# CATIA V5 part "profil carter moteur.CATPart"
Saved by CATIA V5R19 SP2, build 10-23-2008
Part number: profil carter moteur
Bounding box of the stored display mesh (mm): x -35 to 35, y -34 to 34, z 0 to 135
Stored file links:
  Z:\fausse table rondelle-20220905T211342Z-001\fausse table rondelle\profil carter moteur.CATPart
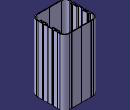
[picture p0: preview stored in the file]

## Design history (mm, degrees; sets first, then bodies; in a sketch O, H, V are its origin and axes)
AxisSystem1: origin (0, 0, 0), X (1, 0, 0), Y (0, 1, 0), Z (0, 0, 1)
Body1 (main body)
  Sketch1 on XY plane of AxisSystem1, origin (0, 0, 0), H (1, 0, 0), V (0, 1, 0)
    line L1 (-25, 34) -> (-20.2, 34)
    line L2 (-35, 0.2) -> (-35, 8.4)
    arc A1 centre (-25, 24) radius 10 from (-25, 34) to (-35, 24) ccw
    point P1 (-25, 34)
    point P2 (-35, 24)
    line L3 (-20.2, 34) -> (-20, 33.8)
    point P4 (-20, 33.8)
    line L4 (-20, 33.8) -> (-19.8, 34)
    construction line L5 (-20, 40.5053) -> (-20, 28.8065)
    point P5 (-20, 40.5053)
    point P6 (-20, 28.8065)
    line L6 (-19.8, 34) -> (-0.2, 34)
    point P7 (-20.2, 34)
    point P8 (-19.8, 34)
    construction line L7 (0, 34) -> (0, 0)
    construction line L8 (-35, 0) -> (38.6581, 0)
    point P9 (38.6581, 0)
    point P10 (0, 0)
    point P11 (0, 34)
    point P12 (-35, 0)
    line L9 (-0.2, 34) -> (0, 33.8)
    point P13 (0, 33.8)
    point P14 (-0.2, 34)
    reference projected line E1 through (0, 0) direction (0, 1) from edge [YZ plane of AxisSystem1 | XY plane of AxisSystem1]
    point P15 (0, 32.5)
    line L10 (0, 32.5) -> (-25, 32.5)
    point P16 (-25, 32.5)
    arc A2 centre (-25, 24) radius 8.5 from (-25, 32.5) to (-33.5, 24) ccw
    point P18 (-33.5, 24)
    line L11 (-33.5, 24) -> (-33.5, 19.15)
    point P19 (-33.5, 19.15)
    line L12 (-33.5, 19.15) -> (-30, 19.15)
    point P20 (-30, 19.15)
    line L13 (-30, 19.15) -> (-30, 17)
    point P21 (-30, 17)
    line L14 (-30, 17) -> (-30.6876, 17)
    point P22 (-30.6876, 17)
    arc A3 centre (-32, 16) radius 1.65 from (-30.6876, 17) to (-30.6876, 15) ccw
    point P23 (-32, 16)
    point P24 (-30.6876, 15)
    line L15 (-30.6876, 15) -> (-30, 15)
    point P25 (-30, 15)
    line L16 (-30, 15) -> (-30, 5.65)
    point P26 (-30, 5.65)
    line L17 (-30, 5.65) -> (-33.5, 5.65)
    point P27 (-33.5, 5.65)
    line L18 (-33.5, 5.65) -> (-33.5, 0)
    point P28 (-33.5, 0)
    construction line L19 (-39.3209, 20) -> (-28.5194, 20)
    point P29 (-39.3209, 20)
    point P30 (-28.5194, 20)
    construction line L20 (-39.519, 10) -> (-27.1443, 10)
    point P31 (-39.519, 10)
    point P32 (-27.1443, 10)
    axis line L21 (-33.2034, 16) -> (-30.7966, 16)
    point P33 (-33.2034, 16)
    point P34 (-30.7966, 16)
    reference projected line E2 through (0, 0) direction (1, 0) from edge [XY plane of AxisSystem1 | ZX plane of AxisSystem1]
    point P35 (-33.5, 13)
    line L22 (-33.5, 13) -> (-31.5, 13)
    line L23 (-31.5, 13) -> (-31.5, 7)
    line L24 (-31.5, 7) -> (-33.5, 7)
    line L25 (-33.5, 7) -> (-33.5, 8.4)
    point P36 (-31.5, 13)
    point P37 (-31.5, 7)
    point P38 (-33.5, 7)
    line L26 (-35, 11.6) -> (-33.5, 11.6)
    line L27 (-33.5, 8.4) -> (-35, 8.4)
    line L28 (-35, 11.6) -> (-35, 19.8)
    line L29 (-33.5, 11.6) -> (-33.5, 13)
    point P39 (-35, 8.4)
    point P40 (-35, 11.6)
    point P41 (-33.5, 11.6)
    point P42 (-33.5, 8.4)
    line L30 (-35, 19.8) -> (-34.8, 20)
    point P43 (-34.8, 20)
    line L31 (-34.8, 20) -> (-35, 20.2)
    line L32 (-35, 20.2) -> (-35, 24)
    point P44 (-35, 19.8)
    point P45 (-35, 20.2)
    line L33 (-35, 0.2) -> (-34.8, 0)
    point P46 (-34.8, 0)
    point P47 (-35, 0.2)
    reference projected line E3 through (0, 0) direction (0, 1) from edge [YZ plane of AxisSystem1 | XY plane of AxisSystem1]
    point P50 (0, 0)
    construction line L34 through (0, 0) direction (0, 1)
    point P53 (25, 34)
    point P54 (35, 24)
    point P56 (20, 33.8)
    point P57 (20, 28.8065)
    point P58 (20, 40.5053)
    construction line L35 (20, 40.5053) -> (20, 28.8065)
    point P59 (20.2, 34)
    point P60 (19.8, 34)
    point P61 (0, 0)
    point P62 (0, 34)
    construction line L36 (0, 34) -> (0, 0)
    point P63 (35, 0)
    point P64 (0, 33.8)
    point P65 (0.2, 34)
    point P66 (0, 32.5)
    point P67 (25, 32.5)
    point P69 (33.5, 24)
    point P70 (33.5, 19.15)
    point P71 (30, 19.15)
    point P72 (30, 17)
    point P73 (30.6876, 17)
    point P75 (30.6876, 15)
    point P76 (30, 15)
    point P77 (30, 5.65)
    point P78 (33.5, 5.65)
    point P79 (33.5, 0)
    point P80 (28.5194, 20)
    point P81 (39.3209, 20)
    construction line L37 (39.3209, 20) -> (28.5194, 20)
    point P82 (27.1443, 10)
    point P83 (39.519, 10)
    construction line L38 (39.519, 10) -> (27.1443, 10)
    point P84 (30.7966, 16)
    point P85 (33.2034, 16)
    construction line L39 (33.2034, 16) -> (30.7966, 16)
    point P86 (33.5, 13)
    point P87 (31.5, 13)
    point P88 (31.5, 7)
    point P89 (33.5, 7)
    point P90 (35, 8.4)
    point P91 (35, 11.6)
    point P92 (33.5, 11.6)
    point P93 (33.5, 8.4)
    point P94 (34.8, 20)
    point P95 (35, 19.8)
    point P96 (35, 20.2)
    point P97 (34.8, 0)
    point P98 (35, 0.2)
    line L40 (25, 34) -> (20.2, 34)
    line L41 (35, 0.2) -> (35, 8.4)
    arc A4 centre (25, 24) radius 10 from (25, 34) to (35, 24) cw
    line L42 (20.2, 34) -> (20, 33.8)
    line L43 (20, 33.8) -> (19.8, 34)
    line L44 (19.8, 34) -> (0.2, 34)
    line L45 (0.2, 34) -> (0, 33.8)
    line L46 (0, 32.5) -> (25, 32.5)
    arc A5 centre (25, 24) radius 8.5 from (25, 32.5) to (33.5, 24) cw
    line L47 (33.5, 24) -> (33.5, 19.15)
    line L48 (33.5, 19.15) -> (30, 19.15)
    line L49 (30, 19.15) -> (30, 17)
    line L50 (30, 17) -> (30.6876, 17)
    arc A6 centre (32, 16) radius 1.65 from (30.6876, 17) to (30.6876, 15) cw
    line L51 (30.6876, 15) -> (30, 15)
    line L52 (30, 15) -> (30, 5.65)
    line L53 (30, 5.65) -> (33.5, 5.65)
    line L54 (33.5, 5.65) -> (33.5, 0)
    line L55 (33.5, 13) -> (31.5, 13)
    line L56 (31.5, 13) -> (31.5, 7)
    line L57 (31.5, 7) -> (33.5, 7)
    line L58 (33.5, 7) -> (33.5, 8.4)
    line L59 (35, 11.6) -> (33.5, 11.6)
    line L60 (33.5, 8.4) -> (35, 8.4)
    line L61 (35, 11.6) -> (35, 19.8)
    line L62 (33.5, 11.6) -> (33.5, 13)
    line L63 (35, 19.8) -> (34.8, 20)
    line L64 (34.8, 20) -> (35, 20.2)
    line L65 (35, 20.2) -> (35, 24)
    line L66 (35, 0.2) -> (34.8, 0)
    reference projected line E4 through (0, 0) direction (1, 0) from edge [XY plane of AxisSystem1 | ZX plane of AxisSystem1]
    point P101 (0, 0)
    construction line L67 through (0, 0) direction (1, 0)
    construction line L68 through (0, 0) direction (0, -1)
    point P106 (-25, -34)
    point P107 (-35, -24)
    point P109 (-20, -33.8)
    point P110 (-20, -28.8065)
    point P111 (-20, -40.5053)
    construction line L69 (-20, -40.5053) -> (-20, -28.8065)
    point P112 (-20.2, -34)
    point P113 (-19.8, -34)
    point P114 (0, 0)
    point P115 (0, -34)
    construction line L70 (0, -34) -> (0, 0)
    point P116 (38.6581, 0)
    point P117 (-35, 0)
    construction line L71 (-35, 0) -> (38.6581, 0)
    point P118 (0, -33.8)
    point P119 (-0.2, -34)
    point P120 (0, -32.5)
    point P121 (-25, -32.5)
    point P123 (-33.5, -24)
    point P124 (-33.5, -19.15)
    point P125 (-30, -19.15)
    point P126 (-30, -17)
    point P127 (-30.6876, -17)
    point P129 (-30.6876, -15)
    point P130 (-30, -15)
    point P131 (-30, -5.65)
    point P132 (-33.5, -5.65)
    point P133 (-33.5, 0)
    point P134 (-28.5194, -20)
    point P135 (-39.3209, -20)
    construction line L72 (-39.3209, -20) -> (-28.5194, -20)
    point P136 (-27.1443, -10)
    point P137 (-39.519, -10)
    construction line L73 (-39.519, -10) -> (-27.1443, -10)
    point P138 (-30.7966, -16)
    point P139 (-33.2034, -16)
    construction line L74 (-33.2034, -16) -> (-30.7966, -16)
    point P140 (-33.5, -13)
    point P141 (-31.5, -13)
    point P142 (-31.5, -7)
    point P143 (-33.5, -7)
    point P144 (-35, -8.4)
    point P145 (-35, -11.6)
    point P146 (-33.5, -11.6)
    point P147 (-33.5, -8.4)
    point P148 (-34.8, -20)
    point P149 (-35, -19.8)
    point P150 (-35, -20.2)
    point P151 (-34.8, 0)
    point P152 (-35, -0.2)
    point P153 (0, 0)
    point P154 (25, -34)
    point P155 (35, -24)
    point P157 (20, -33.8)
    point P158 (20, -28.8065)
    point P159 (20, -40.5053)
    construction line L75 (20, -40.5053) -> (20, -28.8065)
    point P160 (20.2, -34)
    point P161 (19.8, -34)
    point P162 (0, 0)
    point P163 (0, -34)
    construction line L76 (0, -34) -> (0, 0)
    point P164 (35, 0)
    point P165 (0, -33.8)
    point P166 (0.2, -34)
    point P167 (0, -32.5)
    point P168 (25, -32.5)
    point P170 (33.5, -24)
    point P171 (33.5, -19.15)
    point P172 (30, -19.15)
    point P173 (30, -17)
    point P174 (30.6876, -17)
    point P176 (30.6876, -15)
    point P177 (30, -15)
    point P178 (30, -5.65)
    point P179 (33.5, -5.65)
    point P180 (33.5, 0)
    point P181 (28.5194, -20)
    point P182 (39.3209, -20)
    construction line L77 (39.3209, -20) -> (28.5194, -20)
    point P183 (27.1443, -10)
    point P184 (39.519, -10)
    construction line L78 (39.519, -10) -> (27.1443, -10)
    point P185 (30.7966, -16)
    point P186 (33.2034, -16)
    construction line L79 (33.2034, -16) -> (30.7966, -16)
    point P187 (33.5, -13)
    point P188 (31.5, -13)
    point P189 (31.5, -7)
    point P190 (33.5, -7)
    point P191 (35, -8.4)
    point P192 (35, -11.6)
    point P193 (33.5, -11.6)
    point P194 (33.5, -8.4)
    point P195 (34.8, -20)
    point P196 (35, -19.8)
    point P197 (35, -20.2)
    point P198 (34.8, 0)
    point P199 (35, -0.2)
    line L80 (-25, -34) -> (-20.2, -34)
    line L81 (-35, -0.2) -> (-35, -8.4)
    arc A7 centre (-25, -24) radius 10 from (-25, -34) to (-35, -24) cw
    line L82 (-20.2, -34) -> (-20, -33.8)
    line L83 (-20, -33.8) -> (-19.8, -34)
    line L84 (-19.8, -34) -> (-0.2, -34)
    line L85 (-0.2, -34) -> (0, -33.8)
    line L86 (0, -32.5) -> (-25, -32.5)
    arc A8 centre (-25, -24) radius 8.5 from (-25, -32.5) to (-33.5, -24) cw
    line L87 (-33.5, -24) -> (-33.5, -19.15)
    line L88 (-33.5, -19.15) -> (-30, -19.15)
    line L89 (-30, -19.15) -> (-30, -17)
    line L90 (-30, -17) -> (-30.6876, -17)
    arc A9 centre (-32, -16) radius 1.65 from (-30.6876, -17) to (-30.6876, -15) cw
    line L91 (-30.6876, -15) -> (-30, -15)
    line L92 (-30, -15) -> (-30, -5.65)
    line L93 (-30, -5.65) -> (-33.5, -5.65)
    line L94 (-33.5, -5.65) -> (-33.5, 0)
    line L95 (-33.5, -13) -> (-31.5, -13)
    line L96 (-31.5, -13) -> (-31.5, -7)
    line L97 (-31.5, -7) -> (-33.5, -7)
    line L98 (-33.5, -7) -> (-33.5, -8.4)
    line L99 (-35, -11.6) -> (-33.5, -11.6)
    line L100 (-33.5, -8.4) -> (-35, -8.4)
    line L101 (-35, -11.6) -> (-35, -19.8)
    line L102 (-33.5, -11.6) -> (-33.5, -13)
    line L103 (-35, -19.8) -> (-34.8, -20)
    line L104 (-34.8, -20) -> (-35, -20.2)
    line L105 (-35, -20.2) -> (-35, -24)
    line L106 (-35, -0.2) -> (-34.8, 0)
    line L107 (25, -34) -> (20.2, -34)
    line L108 (35, -0.2) -> (35, -8.4)
    arc A10 centre (25, -24) radius 10 from (25, -34) to (35, -24) ccw
    line L109 (20.2, -34) -> (20, -33.8)
    line L110 (20, -33.8) -> (19.8, -34)
    line L111 (19.8, -34) -> (0.2, -34)
    line L112 (0.2, -34) -> (0, -33.8)
    line L113 (0, -32.5) -> (25, -32.5)
    arc A11 centre (25, -24) radius 8.5 from (25, -32.5) to (33.5, -24) ccw
    line L114 (33.5, -24) -> (33.5, -19.15)
    line L115 (33.5, -19.15) -> (30, -19.15)
    line L116 (30, -19.15) -> (30, -17)
    line L117 (30, -17) -> (30.6876, -17)
    arc A12 centre (32, -16) radius 1.65 from (30.6876, -17) to (30.6876, -15) ccw
    line L118 (30.6876, -15) -> (30, -15)
    line L119 (30, -15) -> (30, -5.65)
    line L120 (30, -5.65) -> (33.5, -5.65)
    line L121 (33.5, -5.65) -> (33.5, 0)
    line L122 (33.5, -13) -> (31.5, -13)
    line L123 (31.5, -13) -> (31.5, -7)
    line L124 (31.5, -7) -> (33.5, -7)
    line L125 (33.5, -7) -> (33.5, -8.4)
    line L126 (35, -11.6) -> (33.5, -11.6)
    line L127 (33.5, -8.4) -> (35, -8.4)
    line L128 (35, -11.6) -> (35, -19.8)
    line L129 (33.5, -11.6) -> (33.5, -13)
    line L130 (35, -19.8) -> (34.8, -20)
    line L131 (34.8, -20) -> (35, -20.2)
    line L132 (35, -20.2) -> (35, -24)
    line L133 (35, -0.2) -> (34.8, 0)
    radius A1 = 10
    distance P4 L1 = 0.2
    distance L5 L2 = 15
    angle L9 L7 = 45
    distance P11 P13 = 0.2
    distance L6 L10 = 1.5
    radius A2 = 8.5
    distance L11 L2 = 1.5
    radius A3 = 1.65
    distance P23 L2 = 3
    distance L14 L15 = 2
    distance L21 L8 = 16
    distance A3 L12 = 1.5
    distance L26 L27 = 3.2
    distance L22 L24 = 6
    distance L25 L2 = 1.5
    distance L25 L23 = 2
    distance L20 L8 = 10
    distance L12 L17 = 13.5
    distance L18 L2 = 1.5
    distance L23 L16 = 1.5
    distance P43 L28 = 0.2
    distance L19 L8 = 20
    angle L33 L8 = 45
    distance P46 L2 = 0.2
    distance L6 L8 = 34
    distance L2 L7 = 35
    horizontal: L1 H, L8 H, L10 H, L12 H, L14 H, L17 H, L19 H, L20 H, L21 H, L22 H, L24 H, L26 H, L27 H
    vertical: L2 V, L5 V, L7 V, L13 V, L16 V, L18 V, L23 V, L25 V
    tangency: A1 L1, A1 L2, A2 L10, L11 A2
    perpendicularity: L4 L3, L5 L1, L31 L30
    symmetry: L4 L3 L5, L14 L15 L21, L26 L27 L20, L24 L22 L20, L30 L31 L19, O P50 E3, V L34 E3, P1 P53 E3, P2 P54 E3, P4 P56 E3, P6 P57 E3, P5 P58 E3, L5 L35 E3, P7 P59 E3, P8 P60 E3, P10 P61 E3, P11 P62 E3, L7 L36 E3, P12 P63 E3, P13 P64 E3, P14 P65 E3, P15 P66 E3, P16 P67 E3, P18 P69 E3, P19 P70 E3, P20 P71 E3, P21 P72 E3, P22 P73 E3, P24 P75 E3, P25 P76 E3, P26 P77 E3, P27 P78 E3, P28 P79 E3, P30 P80 E3, P29 P81 E3, L19 L37 E3, P32 P82 E3, P31 P83 E3, L20 L38 E3, P34 P84 E3, P33 P85 E3, L21 L39 E3, P35 P86 E3, P36 P87 E3, P37 P88 E3, P38 P89 E3, P39 P90 E3, P40 P91 E3, P41 P92 E3, P42 P93 E3, P43 P94 E3, P44 P95 E3, P45 P96 E3, P46 P97 E3, P47 P98 E3, L1 L40 E3, L2 L41 E3, A1 A4 E3, L3 L42 E3, L4 L43 E3, L6 L44 E3, L9 L45 E3, L10 L46 E3, A2 A5 E3, L11 L47 E3, L12 L48 E3, L13 L49 E3, L14 L50 E3, A3 A6 E3, L15 L51 E3, L16 L52 E3, L17 L53 E3, L18 L54 E3, L22 L55 E3, L23 L56 E3, L24 L57 E3, L25 L58 E3, L26 L59 E3, L27 L60 E3, L28 L61 E3, L29 L62 E3, L30 L63 E3, L31 L64 E3, L32 L65 E3, L33 L66 E3, O P101 E4, H L67 E4, V L68 E4, P1 P106 E4, P2 P107 E4, P4 P109 E4, P6 P110 E4, P5 P111 E4, L5 L69 E4, P7 P112 E4, P8 P113 E4, P10 P114 E4, P11 P115 E4, L7 L70 E4, P9 P116 E4, P12 P117 E4, L8 L71 E4, P13 P118 E4, P14 P119 E4, P15 P120 E4, P16 P121 E4, P18 P123 E4, P19 P124 E4, P20 P125 E4, P21 P126 E4, P22 P127 E4, P24 P129 E4, P25 P130 E4, P26 P131 E4, P27 P132 E4, P28 P133 E4, P30 P134 E4, P29 P135 E4, L19 L72 E4, P32 P136 E4, P31 P137 E4, L20 L73 E4, P34 P138 E4, P33 P139 E4, L21 L74 E4, P35 P140 E4, P36 P141 E4, P37 P142 E4, P38 P143 E4, P39 P144 E4, P40 P145 E4, P41 P146 E4, P42 P147 E4, P43 P148 E4, P44 P149 E4, P45 P150 E4, P46 P151 E4, P47 P152 E4, P50 P153 E4, P53 P154 E4, P54 P155 E4, P56 P157 E4, P57 P158 E4, P58 P159 E4, L35 L75 E4, P59 P160 E4, P60 P161 E4, P61 P162 E4, P62 P163 E4, L36 L76 E4, P63 P164 E4, P64 P165 E4, P65 P166 E4, P66 P167 E4, P67 P168 E4, P69 P170 E4, P70 P171 E4, P71 P172 E4, P72 P173 E4, P73 P174 E4, P75 P176 E4, P76 P177 E4, P77 P178 E4, P78 P179 E4, P79 P180 E4, P80 P181 E4, P81 P182 E4, L37 L77 E4, P82 P183 E4, P83 P184 E4, L38 L78 E4, P84 P185 E4, P85 P186 E4, L39 L79 E4, P86 P187 E4, P87 P188 E4, P88 P189 E4, P89 P190 E4, P90 P191 E4, P91 P192 E4, P92 P193 E4, P93 P194 E4, P94 P195 E4, P95 P196 E4, P96 P197 E4, P97 P198 E4, P98 P199 E4, L1 L80 E4, L2 L81 E4, A1 A7 E4, L3 L82 E4, L4 L83 E4, L6 L84 E4, L9 L85 E4, L10 L86 E4, A2 A8 E4, L11 L87 E4, L12 L88 E4, L13 L89 E4, L14 L90 E4, A3 A9 E4, L15 L91 E4, L16 L92 E4, L17 L93 E4, L18 L94 E4, L22 L95 E4, L23 L96 E4, L24 L97 E4, L25 L98 E4, L26 L99 E4, L27 L100 E4, L28 L101 E4, L29 L102 E4, L30 L103 E4, L31 L104 E4, L32 L105 E4, L33 L106 E4, L40 L107 E4, L41 L108 E4, A4 A10 E4, L42 L109 E4, L43 L110 E4, L44 L111 E4, L45 L112 E4, L46 L113 E4, A5 A11 E4, L47 L114 E4, L48 L115 E4, L49 L116 E4, L50 L117 E4, A6 A12 E4, L51 L118 E4, L52 L119 E4, L53 L120 E4, L54 L121 E4, L55 L122 E4, L56 L123 E4, L57 L124 E4, L58 L125 E4, L59 L126 E4, L60 L127 E4, L61 L128 E4, L62 L129 E4, L63 L130 E4, L64 L131 E4, L65 L132 E4, L66 L133 E4
    coincidence: L1 L6, P10 L8, P13 L7, P11 L6, L7 E1, P15 L7, P25 L13, P28 L8, L8 E2, L2 L28, L25 L29, P43 L19, L28 L32, P46 L8, P12 L2, P13 P64, P15 P66, P28 P133, P46 P151, P79 P180, P97 P198, P118 P165, P120 P167
    midpoint: P23 L21
  Pad1: profile Sketch1, direction (0, 0, 1), length 135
